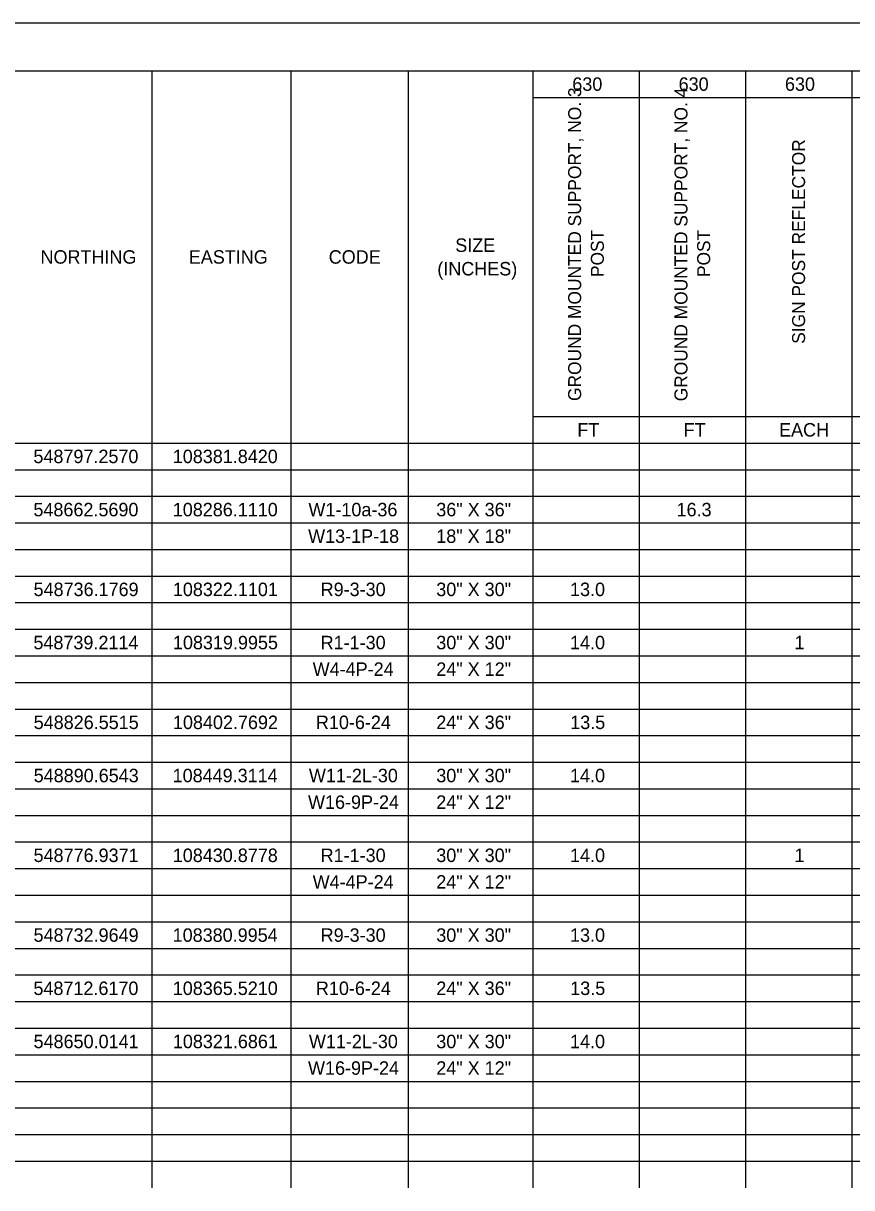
# Model space of a CAD drawing. Extents: x 0 to 34, y 0 to 22.
# Drawn here: x 7.6 to 16.33, y 9.74 to 22 of the extents above; entities that cross this region are included whole.
import ezdxf

# ---------------------------------------------------------------- set-up
doc = ezdxf.new("R2010")
doc.units = 0
for name, color, linetype in [('SH_Border', 7, 'Continuous'), ('SH_Cut_Line', 7, 'Continuous'), ('SH_Data', 7, 'Continuous')]:
    doc.layers.add(name, color=color, linetype=linetype)

msp = doc.modelspace()

# ---------------------------------------------------------------- linework, layer by layer
at = {"layer": 'SH_Border'}
msp.add_lwpolyline([(1.5, 21.5), (33.5, 21.5), (33.5, 0.5), (1.5, 0.5)], close=True, dxfattribs=at)
at = {"layer": 'SH_Cut_Line'}
msp.add_lwpolyline([(0, 0), (34, 0), (34, 22), (0, 22)], close=True, dxfattribs=at)
at = {"layer": 'SH_Data'}
for p, q in [((1.5, 21.5), (8.951, 21.5)), ((8.951, 21.5), (10.418, 21.5)), ((8.951, 21.5), (8.951, 21.22)), ((10.418, 21.5), (11.654, 21.5)), ((10.418, 21.5), (10.418, 21.22)), ((11.654, 21.5), (14.086, 21.5)), ((11.654, 21.5), (11.654, 21.22)), ((12.966, 21.5), (12.966, 21.22)), ((14.086, 21.5), (15.206, 21.5)), ((14.086, 21.5), (14.086, 21.22)), ((15.206, 21.5), (16.325, 21.5)), ((15.206, 21.5), (15.206, 21.22)), ((16.325, 21.5), (24.163, 21.5)), ((16.325, 21.5), (16.325, 21.22)), ((8.951, 21.22), (8.951, 20.94)), ((10.418, 21.22), (10.418, 20.94)), ((11.654, 21.22), (11.654, 20.94)), ((12.966, 21.22), (14.086, 21.22)), ((12.966, 21.22), (12.966, 20.94)), ((14.086, 21.22), (15.206, 21.22)), ((14.086, 21.22), (14.086, 20.94)), ((15.206, 21.22), (16.325, 21.22)), ((15.206, 21.22), (15.206, 20.94)), ((16.325, 21.22), (24.163, 21.22)), ((16.325, 21.22), (16.325, 20.94)), ((8.951, 20.94), (8.951, 20.66)), ((10.418, 20.94), (10.418, 20.66)), ((11.654, 20.94), (11.654, 20.66)), ((12.966, 20.94), (12.966, 20.66)), ((14.086, 20.94), (14.086, 20.66)), ((15.206, 20.94), (15.206, 20.66)), ((16.325, 20.94), (16.325, 20.66)), ((8.951, 20.66), (8.951, 20.38)), ((10.418, 20.66), (10.418, 20.38)), ((11.654, 20.66), (11.654, 20.38)), ((12.966, 20.66), (12.966, 20.38)), ((14.086, 20.66), (14.086, 20.38)), ((15.206, 20.66), (15.206, 20.38)), ((16.325, 20.66), (16.325, 20.38)), ((8.951, 20.38), (8.951, 20.1)), ((10.418, 20.38), (10.418, 20.1)), ((11.654, 20.38), (11.654, 20.1)), ((12.966, 20.38), (12.966, 20.1)), ((14.086, 20.38), (14.086, 20.1)), ((15.206, 20.38), (15.206, 20.1)), ((16.325, 20.38), (16.325, 20.1)), ((8.951, 20.1), (8.951, 19.82)), ((10.418, 20.1), (10.418, 19.82)), ((11.654, 20.1), (11.654, 19.82)), ((12.966, 20.1), (12.966, 19.82)), ((14.086, 20.1), (14.086, 19.82)), ((15.206, 20.1), (15.206, 19.82)), ((16.325, 20.1), (16.325, 19.82)), ((8.951, 19.82), (8.951, 19.54)), ((10.418, 19.82), (10.418, 19.54)), ((11.654, 19.82), (11.654, 19.54)), ((12.966, 19.82), (12.966, 19.54)), ((14.086, 19.82), (14.086, 19.54)), ((15.206, 19.82), (15.206, 19.54)), ((16.325, 19.82), (16.325, 19.54)), ((8.951, 19.54), (8.951, 18.98)), ((10.418, 19.54), (10.418, 18.98)), ((11.654, 19.54), (11.654, 18.98)), ((12.966, 19.54), (12.966, 18.98)), ((14.086, 19.54), (14.086, 18.98)), ((15.206, 19.54), (15.206, 18.98)), ((16.325, 19.54), (16.325, 18.98)), ((8.951, 18.98), (8.951, 18.14)), ((10.418, 18.98), (10.418, 18.14)), ((11.654, 18.98), (11.654, 18.14)), ((12.966, 18.98), (12.966, 18.14)), ((14.086, 18.98), (14.086, 18.14)), ((15.206, 18.98), (15.206, 18.14)), ((16.325, 18.98), (16.325, 18.14)), ((8.951, 18.14), (8.951, 17.86)), ((10.418, 18.14), (10.418, 17.86)), ((11.654, 18.14), (11.654, 17.86)), ((12.966, 18.14), (12.966, 17.86)), ((14.086, 18.14), (14.086, 17.86)), ((15.206, 18.14), (15.206, 17.86)), ((16.325, 18.14), (16.325, 17.86)), ((8.951, 17.86), (8.951, 17.3)), ((10.418, 17.86), (10.418, 17.3)), ((11.654, 17.86), (11.654, 17.3)), ((12.966, 17.86), (14.086, 17.86)), ((12.966, 17.86), (12.966, 17.3)), ((14.086, 17.86), (15.206, 17.86)), ((14.086, 17.86), (14.086, 17.3)), ((15.206, 17.86), (16.325, 17.86)), ((15.206, 17.86), (15.206, 17.3)), ((16.325, 17.86), (24.163, 17.86)), ((16.325, 17.86), (16.325, 17.3)), ((1.5, 17.58), (8.951, 17.58)), ((8.951, 17.58), (10.418, 17.58)), ((10.418, 17.58), (11.654, 17.58)), ((11.654, 17.58), (14.086, 17.58)), ((14.086, 17.58), (15.206, 17.58)), ((15.206, 17.58), (16.325, 17.58)), ((16.325, 17.58), (24.163, 17.58)), ((1.5, 17.3), (8.951, 17.3)), ((8.951, 17.3), (10.418, 17.3)), ((8.951, 17.3), (8.951, 17.02)), ((10.418, 17.3), (11.654, 17.3)), ((10.418, 17.3), (10.418, 17.02)), ((11.654, 17.3), (14.086, 17.3)), ((11.654, 17.3), (11.654, 17.02)), ((12.966, 17.3), (12.966, 17.02)), ((14.086, 17.3), (15.206, 17.3)), ((14.086, 17.3), (14.086, 17.02)), ((15.206, 17.3), (16.325, 17.3)), ((15.206, 17.3), (15.206, 17.02)), ((16.325, 17.3), (24.163, 17.3)), ((16.325, 17.3), (16.325, 17.02)), ((1.5, 17.02), (8.951, 17.02)), ((8.951, 17.02), (10.418, 17.02)), ((8.951, 17.02), (8.951, 15.9)), ((10.418, 17.02), (11.654, 17.02)), ((10.418, 17.02), (10.418, 15.9)), ((11.654, 17.02), (14.086, 17.02)), ((11.654, 17.02), (11.654, 15.9)), ((12.966, 17.02), (12.966, 15.9)), ((14.086, 17.02), (15.206, 17.02)), ((14.086, 17.02), (14.086, 15.9)), ((15.206, 17.02), (16.325, 17.02)), ((15.206, 17.02), (15.206, 15.9)), ((16.325, 17.02), (24.163, 17.02)), ((16.325, 17.02), (16.325, 15.9)), ((1.5, 16.74), (8.951, 16.74)), ((8.951, 16.74), (10.418, 16.74)), ((10.418, 16.74), (11.654, 16.74)), ((11.654, 16.74), (14.086, 16.74)), ((14.086, 16.74), (15.206, 16.74)), ((15.206, 16.74), (16.325, 16.74)), ((16.325, 16.74), (24.163, 16.74)), ((1.5, 16.46), (8.951, 16.46)), ((8.951, 16.46), (10.418, 16.46)), ((10.418, 16.46), (11.654, 16.46)), ((11.654, 16.46), (14.086, 16.46)), ((14.086, 16.46), (15.206, 16.46)), ((15.206, 16.46), (16.325, 16.46)), ((16.325, 16.46), (24.163, 16.46)), ((1.5, 16.18), (8.951, 16.18)), ((8.951, 16.18), (10.418, 16.18)), ((10.418, 16.18), (11.654, 16.18)), ((11.654, 16.18), (14.086, 16.18)), ((14.086, 16.18), (15.206, 16.18)), ((15.206, 16.18), (16.325, 16.18)), ((16.325, 16.18), (24.163, 16.18)), ((1.5, 15.9), (8.951, 15.9)), ((8.951, 15.9), (10.418, 15.9)), ((8.951, 15.9), (8.951, 15.62)), ((10.418, 15.9), (11.654, 15.9)), ((10.418, 15.9), (10.418, 15.62)), ((11.654, 15.9), (14.086, 15.9)), ((11.654, 15.9), (11.654, 15.62)), ((12.966, 15.9), (12.966, 15.62)), ((14.086, 15.9), (15.206, 15.9)), ((14.086, 15.9), (14.086, 15.62)), ((15.206, 15.9), (16.325, 15.9)), ((15.206, 15.9), (15.206, 15.62)), ((16.325, 15.9), (24.163, 15.9)), ((16.325, 15.9), (16.325, 15.62)), ((1.5, 15.62), (8.951, 15.62)), ((8.951, 15.62), (10.418, 15.62)), ((8.951, 15.62), (8.951, 15.06)), ((10.418, 15.62), (11.654, 15.62)), ((10.418, 15.62), (10.418, 15.06)), ((11.654, 15.62), (14.086, 15.62)), ((11.654, 15.62), (11.654, 15.06)), ((12.966, 15.62), (12.966, 15.06)), ((14.086, 15.62), (15.206, 15.62)), ((14.086, 15.62), (14.086, 15.06)), ((15.206, 15.62), (16.325, 15.62)), ((15.206, 15.62), (15.206, 15.06)), ((16.325, 15.62), (24.163, 15.62)), ((16.325, 15.62), (16.325, 15.06)), ((1.5, 15.34), (8.951, 15.34)), ((8.951, 15.34), (10.418, 15.34)), ((10.418, 15.34), (11.654, 15.34)), ((11.654, 15.34), (14.086, 15.34)), ((14.086, 15.34), (15.206, 15.34)), ((15.206, 15.34), (16.325, 15.34)), ((16.325, 15.34), (24.163, 15.34)), ((1.5, 15.06), (8.951, 15.06)), ((8.951, 15.06), (10.418, 15.06)), ((8.951, 15.06), (8.951, 14.5)), ((10.418, 15.06), (11.654, 15.06)), ((10.418, 15.06), (10.418, 14.5)), ((11.654, 15.06), (14.086, 15.06)), ((11.654, 15.06), (11.654, 14.5)), ((12.966, 15.06), (12.966, 14.5)), ((14.086, 15.06), (15.206, 15.06)), ((14.086, 15.06), (14.086, 14.5)), ((15.206, 15.06), (16.325, 15.06)), ((15.206, 15.06), (15.206, 14.5)), ((16.325, 15.06), (24.163, 15.06)), ((16.325, 15.06), (16.325, 14.5)), ((1.5, 14.78), (8.951, 14.78)), ((8.951, 14.78), (10.418, 14.78)), ((10.418, 14.78), (11.654, 14.78)), ((11.654, 14.78), (14.086, 14.78)), ((14.086, 14.78), (15.206, 14.78)), ((15.206, 14.78), (16.325, 14.78)), ((16.325, 14.78), (24.163, 14.78)), ((1.5, 14.5), (8.951, 14.5)), ((8.951, 14.5), (10.418, 14.5)), ((8.951, 14.5), (8.951, 14.22)), ((10.418, 14.5), (11.654, 14.5)), ((10.418, 14.5), (10.418, 14.22)), ((11.654, 14.5), (14.086, 14.5)), ((11.654, 14.5), (11.654, 14.22)), ((12.966, 14.5), (12.966, 14.22)), ((14.086, 14.5), (15.206, 14.5)), ((14.086, 14.5), (14.086, 14.22)), ((15.206, 14.5), (16.325, 14.5)), ((15.206, 14.5), (15.206, 14.22)), ((16.325, 14.5), (24.163, 14.5)), ((16.325, 14.5), (16.325, 14.22)), ((1.5, 14.22), (8.951, 14.22)), ((8.951, 14.22), (10.418, 14.22)), ((8.951, 14.22), (8.951, 13.66)), ((10.418, 14.22), (11.654, 14.22)), ((10.418, 14.22), (10.418, 13.66)), ((11.654, 14.22), (14.086, 14.22)), ((11.654, 14.22), (11.654, 13.66)), ((12.966, 14.22), (12.966, 13.66)), ((14.086, 14.22), (15.206, 14.22)), ((14.086, 14.22), (14.086, 13.66)), ((15.206, 14.22), (16.325, 14.22)), ((15.206, 14.22), (15.206, 13.66)), ((16.325, 14.22), (24.163, 14.22)), ((16.325, 14.22), (16.325, 13.66)), ((1.5, 13.94), (8.951, 13.94)), ((8.951, 13.94), (10.418, 13.94)), ((10.418, 13.94), (11.654, 13.94)), ((11.654, 13.94), (14.086, 13.94)), ((14.086, 13.94), (15.206, 13.94)), ((15.206, 13.94), (16.325, 13.94)), ((16.325, 13.94), (24.163, 13.94)), ((1.5, 13.66), (8.951, 13.66)), ((8.951, 13.66), (10.418, 13.66)), ((8.951, 13.66), (8.951, 13.38)), ((10.418, 13.66), (11.654, 13.66)), ((10.418, 13.66), (10.418, 13.38)), ((11.654, 13.66), (14.086, 13.66)), ((11.654, 13.66), (11.654, 13.38)), ((12.966, 13.66), (12.966, 13.38)), ((14.086, 13.66), (15.206, 13.66)), ((14.086, 13.66), (14.086, 13.38)), ((15.206, 13.66), (16.325, 13.66)), ((15.206, 13.66), (15.206, 13.38)), ((16.325, 13.66), (24.163, 13.66)), ((16.325, 13.66), (16.325, 13.38)), ((1.5, 13.38), (8.951, 13.38)), ((8.951, 13.38), (10.418, 13.38)), ((8.951, 13.38), (8.951, 12.54)), ((10.418, 13.38), (11.654, 13.38)), ((10.418, 13.38), (10.418, 12.54)), ((11.654, 13.38), (14.086, 13.38)), ((11.654, 13.38), (11.654, 12.54)), ((12.966, 13.38), (12.966, 12.54)), ((14.086, 13.38), (15.206, 13.38)), ((14.086, 13.38), (14.086, 12.54)), ((15.206, 13.38), (16.325, 13.38)), ((15.206, 13.38), (15.206, 12.54)), ((16.325, 13.38), (24.163, 13.38)), ((16.325, 13.38), (16.325, 12.54)), ((1.5, 13.1), (8.951, 13.1)), ((8.951, 13.1), (10.418, 13.1)), ((10.418, 13.1), (11.654, 13.1)), ((11.654, 13.1), (14.086, 13.1)), ((14.086, 13.1), (15.206, 13.1)), ((15.206, 13.1), (16.325, 13.1)), ((16.325, 13.1), (24.163, 13.1)), ((1.5, 12.82), (8.951, 12.82)), ((8.951, 12.82), (10.418, 12.82)), ((10.418, 12.82), (11.654, 12.82)), ((11.654, 12.82), (14.086, 12.82)), ((14.086, 12.82), (15.206, 12.82)), ((15.206, 12.82), (16.325, 12.82)), ((16.325, 12.82), (24.163, 12.82)), ((1.5, 12.54), (8.951, 12.54)), ((8.951, 12.54), (10.418, 12.54)), ((8.951, 12.54), (8.951, 11.98)), ((10.418, 12.54), (11.654, 12.54)), ((10.418, 12.54), (10.418, 11.98)), ((11.654, 12.54), (14.086, 12.54)), ((11.654, 12.54), (11.654, 11.98)), ((12.966, 12.54), (12.966, 11.98)), ((14.086, 12.54), (15.206, 12.54)), ((14.086, 12.54), (14.086, 11.98)), ((15.206, 12.54), (16.325, 12.54)), ((15.206, 12.54), (15.206, 11.98)), ((16.325, 12.54), (24.163, 12.54)), ((16.325, 12.54), (16.325, 11.98)), ((1.5, 12.26), (8.951, 12.26)), ((8.951, 12.26), (10.418, 12.26)), ((10.418, 12.26), (11.654, 12.26)), ((11.654, 12.26), (14.086, 12.26)), ((14.086, 12.26), (15.206, 12.26)), ((15.206, 12.26), (16.325, 12.26)), ((16.325, 12.26), (24.163, 12.26)), ((1.5, 11.98), (8.951, 11.98)), ((8.951, 11.98), (10.418, 11.98)), ((8.951, 11.98), (8.951, 11.14)), ((10.418, 11.98), (11.654, 11.98)), ((10.418, 11.98), (10.418, 11.14)), ((11.654, 11.98), (14.086, 11.98)), ((11.654, 11.98), (11.654, 11.14)), ((12.966, 11.98), (12.966, 11.14)), ((14.086, 11.98), (15.206, 11.98)), ((14.086, 11.98), (14.086, 11.14)), ((15.206, 11.98), (16.325, 11.98)), ((15.206, 11.98), (15.206, 11.14)), ((16.325, 11.98), (24.163, 11.98)), ((16.325, 11.98), (16.325, 11.14)), ((1.5, 11.7), (8.951, 11.7)), ((8.951, 11.7), (10.418, 11.7)), ((10.418, 11.7), (11.654, 11.7)), ((11.654, 11.7), (14.086, 11.7)), ((14.086, 11.7), (15.206, 11.7)), ((15.206, 11.7), (16.325, 11.7)), ((16.325, 11.7), (24.163, 11.7)), ((1.5, 11.42), (8.951, 11.42)), ((8.951, 11.42), (10.418, 11.42)), ((10.418, 11.42), (11.654, 11.42)), ((11.654, 11.42), (14.086, 11.42)), ((14.086, 11.42), (15.206, 11.42)), ((15.206, 11.42), (16.325, 11.42)), ((16.325, 11.42), (24.163, 11.42)), ((1.5, 11.14), (8.951, 11.14)), ((8.951, 11.14), (10.418, 11.14)), ((8.951, 11.14), (8.951, 10.58)), ((10.418, 11.14), (11.654, 11.14)), ((10.418, 11.14), (10.418, 10.58)), ((11.654, 11.14), (14.086, 11.14)), ((11.654, 11.14), (11.654, 10.58)), ((12.966, 11.14), (12.966, 10.58)), ((14.086, 11.14), (15.206, 11.14)), ((14.086, 11.14), (14.086, 10.58)), ((15.206, 11.14), (16.325, 11.14)), ((15.206, 11.14), (15.206, 10.58)), ((16.325, 11.14), (24.163, 11.14)), ((16.325, 11.14), (16.325, 10.58)), ((1.5, 10.86), (8.951, 10.86)), ((8.951, 10.86), (10.418, 10.86)), ((10.418, 10.86), (11.654, 10.86)), ((11.654, 10.86), (14.086, 10.86)), ((14.086, 10.86), (15.206, 10.86)), ((15.206, 10.86), (16.325, 10.86)), ((16.325, 10.86), (24.163, 10.86)), ((1.5, 10.58), (8.951, 10.58)), ((8.951, 10.58), (10.418, 10.58)), ((8.951, 10.58), (8.951, 9.74)), ((10.418, 10.58), (11.654, 10.58)), ((10.418, 10.58), (10.418, 9.74)), ((11.654, 10.58), (14.086, 10.58)), ((11.654, 10.58), (11.654, 9.74)), ((12.966, 10.58), (12.966, 9.74)), ((14.086, 10.58), (15.206, 10.58)), ((14.086, 10.58), (14.086, 9.74)), ((15.206, 10.58), (16.325, 10.58)), ((15.206, 10.58), (15.206, 9.74)), ((16.325, 10.58), (24.163, 10.58)), ((16.325, 10.58), (16.325, 9.74)), ((1.5, 10.3), (8.951, 10.3)), ((8.951, 10.3), (10.418, 10.3)), ((10.418, 10.3), (11.654, 10.3)), ((11.654, 10.3), (14.086, 10.3)), ((14.086, 10.3), (15.206, 10.3)), ((15.206, 10.3), (16.325, 10.3)), ((16.325, 10.3), (24.163, 10.3)), ((1.5, 10.02), (8.951, 10.02)), ((8.951, 10.02), (10.418, 10.02)), ((10.418, 10.02), (11.654, 10.02)), ((11.654, 10.02), (14.086, 10.02)), ((14.086, 10.02), (15.206, 10.02)), ((15.206, 10.02), (16.325, 10.02)), ((16.325, 10.02), (24.163, 10.02))]:
    msp.add_line(p, q, dxfattribs=at)

# ---------------------------------------------------------------- texts
for s, height, p in [('630', 0.1417, (13.382, 21.289)), ('630', 0.1417, (14.502, 21.289)), ('630', 0.1417, (15.622, 21.289)), ('SIZE', 0.1417, (12.149, 19.593)), ('NORTHING', 0.1417, (7.78, 19.469)), ('EASTING', 0.1417, (9.342, 19.469)), ('CODE', 0.1417, (10.816, 19.469)), ('(INCHES)', 0.1417, (11.96, 19.345)), ('FT', 0.1417, (13.435, 17.649)), ('FT', 0.1417, (14.555, 17.649)), ('EACH', 0.1417, (15.56, 17.649)), ('548797.2570', 0.14167, (7.705, 17.369)), ('108381.8420', 0.14167, (9.173, 17.369)), ('548662.5690', 0.14167, (7.705, 16.809)), ('108286.1110', 0.14167, (9.173, 16.809)), ('W1-10a-36', 0.1417, (10.602, 16.809)), ('36" X 36"', 0.1417, (11.949, 16.809)), ('16.3', 0.1417, (14.48, 16.809)), ('W13-1P-18', 0.1417, (10.599, 16.529)), ('18" X 18"', 0.1417, (11.949, 16.529)), ('548736.1769', 0.14167, (7.707, 15.969)), ('108322.1101', 0.14167, (9.174, 15.969)), ('R9-3-30', 0.1417, (10.731, 15.969)), ('30" X 30"', 0.1417, (11.949, 15.969)), ('13.0', 0.1417, (13.358, 15.969)), ('548739.2114', 0.14167, (7.705, 15.409)), ('108319.9955', 0.14167, (9.175, 15.409)), ('R1-1-30', 0.1417, (10.731, 15.409)), ('30" X 30"', 0.1417, (11.949, 15.409)), ('14.0', 0.1417, (13.358, 15.409)), ('1', 0.142, (15.722, 15.409)), ('W4-4P-24', 0.1417, (10.647, 15.129)), ('24" X 12"', 0.1417, (11.949, 15.129)), ('548826.5515', 0.14167, (7.708, 14.569)), ('108402.7692', 0.14167, (9.175, 14.569)), ('R10-6-24', 0.1417, (10.681, 14.569)), ('24" X 36"', 0.1417, (11.949, 14.569)), ('13.5', 0.1417, (13.36, 14.569)), ('548890.6543', 0.14167, (7.708, 14.009)), ('108449.3114', 0.14167, (9.172, 14.009)), ('W11-2L-30', 0.1417, (10.607, 14.009)), ('30" X 30"', 0.1417, (11.949, 14.009)), ('14.0', 0.1417, (13.358, 14.009)), ('W16-9P-24', 0.1417, (10.598, 13.729)), ('24" X 12"', 0.1417, (11.949, 13.729)), ('548776.9371', 0.14167, (7.707, 13.169)), ('108430.8778', 0.14167, (9.173, 13.169)), ('R1-1-30', 0.1417, (10.731, 13.169)), ('30" X 30"', 0.1417, (11.949, 13.169)), ('14.0', 0.1417, (13.358, 13.169)), ('1', 0.142, (15.722, 13.169)), ('W4-4P-24', 0.1417, (10.647, 12.889)), ('24" X 12"', 0.1417, (11.949, 12.889)), ('548732.9649', 0.14167, (7.707, 12.329)), ('108380.9954', 0.14167, (9.172, 12.329)), ('R9-3-30', 0.1417, (10.731, 12.329)), ('30" X 30"', 0.1417, (11.949, 12.329)), ('13.0', 0.1417, (13.358, 12.329)), ('548712.6170', 0.14167, (7.705, 11.769)), ('108365.5210', 0.14167, (9.173, 11.769)), ('R10-6-24', 0.1417, (10.681, 11.769)), ('24" X 36"', 0.1417, (11.949, 11.769)), ('13.5', 0.1417, (13.36, 11.769)), ('548650.0141', 0.14167, (7.707, 11.209)), ('108321.6861', 0.14167, (9.174, 11.209)), ('W11-2L-30', 0.1417, (10.607, 11.209)), ('30" X 30"', 0.1417, (11.949, 11.209)), ('14.0', 0.1417, (13.358, 11.209)), ('W16-9P-24', 0.1417, (10.598, 10.929)), ('24" X 12"', 0.1417, (11.949, 10.929))]:
    msp.add_text(s, height=height, dxfattribs=at).set_placement(p)
for s, height, p in [('GROUND MOUNTED SUPPORT, NO. 3 ', 0.13674, (13.475, 18.023)), ('GROUND MOUNTED SUPPORT, NO. 4 ', 0.13674, (14.595, 18.02)), ('SIGN POST REFLECTOR', 0.13674, (15.834, 18.625)), ('POST', 0.1367, (13.714, 19.328)), ('POST', 0.1367, (14.834, 19.328))]:
    msp.add_text(s, height=height, rotation=90, dxfattribs=at).set_placement(p)

doc.saveas('drawing.dxf')
